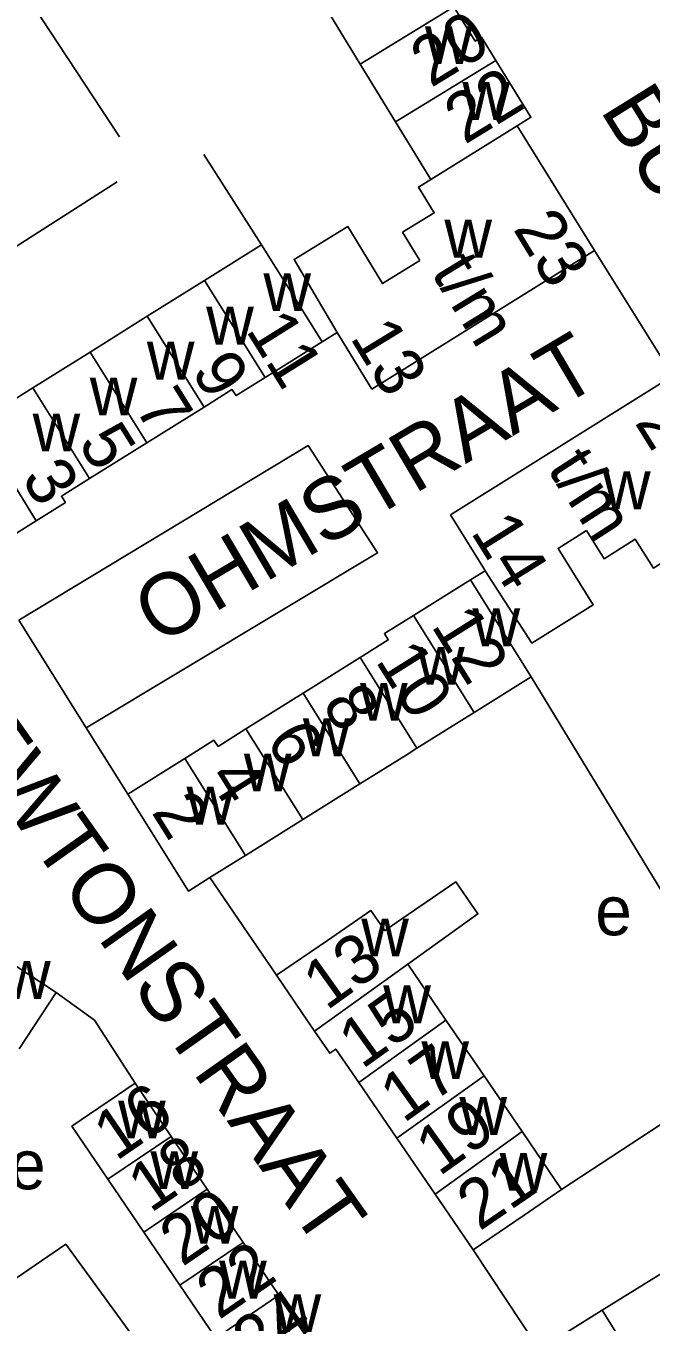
# Model space of a CAD drawing. Extents: x 159294 to 161936, y 384538 to 386517.
# Drawn here: x 159801.9 to 159852.7, y 385204 to 385309.2 of the extents above; entities that cross this region are included whole.
import ezdxf

# ---------------------------------------------------------------- set-up
doc = ezdxf.new("R2010")
doc.units = 0
for name, color, linetype in [('BLT_Basislijn', 7, 'Continuous'), ('BLT_Bebouwing', 7, 'Continuous'), ('BLT_Centroide', 7, 'Continuous'), ('BLT_Huisnummer', 7, 'Continuous'), ('BLT_Huisnummer_ tussenligend', 7, 'Continuous'), ('BLT_Huisnummer_reeks', 7, 'Continuous'), ('BLT_Onderverdeling_panden', 7, 'Continuous'), ('BLT_Straatnaam', 7, 'Continuous')]:
    doc.layers.add(name, color=color, linetype=linetype)

msp = doc.modelspace()

# ---------------------------------------------------------------- linework, layer by layer
at = {"layer": 'BLT_Basislijn'}
for p, q in [((159802.47, 385310.92), (159809.5, 385300.22)), ((159821.05, 385291.45), (159816.36, 385298.77)), ((159794.23, 385286.93), (159809.31, 385296.57)), ((159848.11, 385290.99), (159854.48, 385280.81)), ((159825.98, 385283.57), (159827.2, 385284.33)), ((159838.04, 385264.24), (159839.23, 385264.98)), ((159801.33, 385260.97), (159806.79, 385252.22)), ((159842.96, 385256.36), (159859.55, 385229.1)), ((159806.79, 385252.22), (159810.17, 385246.82)), ((159822.27, 385232.13), (159816.85, 385240.05)), ((159804.36, 385230.73), (159807.46, 385228.47)), ((159845.43, 385214.73), (159856.91, 385222.26)), ((159838.25, 385209.82), (159843.61, 385201.74))]:
    msp.add_line(p, q, dxfattribs=at)
for points in [[(159801.33, 385260.97), (159824.83, 385275.15), (159830.47, 385266.43), (159806.79, 385252.22)], [(159810.77, 385223.35), (159807.46, 385228.47)], [(159797.86, 385180.72), (159800.24, 385184.36), (159789.73, 385199.76), (159805.13, 385210.27), (159816, 385195.36), (159820.28, 385198.32)]]:
    msp.add_lwpolyline(points, dxfattribs=at)
at = {"layer": 'BLT_Bebouwing'}
for p, q in [((159829.06, 385306.13), (159826.2, 385310.83)), ((159831.93, 385301.44), (159829.06, 385306.13)), ((159834.8, 385296.75), (159831.93, 385301.44)), ((159841.81, 385301.11), (159844.96, 385296.05)), ((159844.96, 385296.05), (159848.11, 385290.99)), ((159816.41, 385288.55), (159821.05, 385291.45)), ((159848.11, 385290.99), (159830.02, 385279.71)), ((159811.76, 385285.65), (159816.41, 385288.55)), ((159807.11, 385282.74), (159811.76, 385285.65)), ((159821.34, 385280.67), (159825.98, 385283.57)), ((159802.46, 385279.83), (159807.11, 385282.74)), ((159854.48, 385280.81), (159836.39, 385269.52)), ((159797.82, 385276.93), (159802.46, 385279.83)), ((159811.72, 385275.36), (159816.37, 385278.27)), ((159807.07, 385272.46), (159811.72, 385275.36)), ((159798.09, 385266.14), (159802.74, 385269.04)), ((159838.04, 385264.24), (159833.4, 385261.34)), ((159829.07, 385257.94), (159824.42, 385255.04)), ((159838.32, 385253.46), (159842.96, 385256.36)), ((159824.42, 385255.04), (159819.78, 385252.13)), ((159833.68, 385250.56), (159838.32, 385253.46)), ((159814.82, 385249.74), (159810.17, 385246.82)), ((159824.39, 385244.76), (159829.03, 385247.66)), ((159819.74, 385241.86), (159824.39, 385244.76)), ((159832.93, 385233.02), (159836.03, 385228.48)), ((159825.36, 385227.59), (159822.27, 385232.13)), ((159836.03, 385228.48), (159839.13, 385223.95)), ((159810.77, 385223.35), (159813.69, 385219.04)), ((159832.05, 385218.88), (159828.94, 385223.41)), ((159839.13, 385223.95), (159842.23, 385219.42)), ((159813.69, 385219.04), (159816.62, 385214.74)), ((159835.15, 385214.35), (159832.05, 385218.88)), ((159842.23, 385219.42), (159845.43, 385214.73)), ((159808.56, 385215.56), (159811.49, 385211.25)), ((159816.62, 385214.74), (159819.54, 385210.43)), ((159838.25, 385209.82), (159835.15, 385214.35)), ((159811.49, 385211.25), (159814.41, 385206.95)), ((159819.54, 385210.43), (159822.46, 385206.13)), ((159848.73, 385204.93), (159853.84, 385208.1)), ((159814.41, 385206.95), (159817.34, 385202.64)), ((159822.46, 385206.13), (159825.39, 385201.82))]:
    msp.add_line(p, q, dxfattribs=at)
for points in [[(159836.67, 385310.78), (159838.41, 385307.99), (159838.91, 385308.3), (159840.08, 385306.42)], [(159840.08, 385306.42), (159842.94, 385301.81), (159841.81, 385301.11)], [(159833.92, 385290.16), (159832.51, 385292.47), (159835.08, 385294.04), (159833.81, 385296.13), (159834.8, 385296.75)], [(159827.2, 385284.33), (159823.69, 385290.26), (159828.06, 385292.92), (159830.88, 385288.3), (159833.92, 385290.16)], [(159821.05, 385291.45), (159823.33, 385287.81), (159825.98, 385283.57)], [(159830.02, 385279.71), (159827.41, 385283.98), (159827.2, 385284.33)], [(159816.37, 385278.27), (159818.64, 385279.69), (159818.97, 385279.2), (159821.34, 385280.67)], [(159802.74, 385269.04), (159805.1, 385270.51), (159804.78, 385271.03), (159807.07, 385272.46)], [(159836.39, 385269.52), (159839.04, 385265.28), (159839.23, 385264.98)], [(159839.23, 385264.98), (159843.02, 385259.1), (159848, 385262.21), (159845.14, 385266.79), (159847.45, 385268.24)], [(159847.45, 385268.24), (159848.88, 385265.95), (159851.42, 385267.54), (159852.89, 385265.19), (159854.29, 385266.07)], [(159842.96, 385256.36), (159840.69, 385260), (159838.04, 385264.24)], [(159833.4, 385261.34), (159831.03, 385259.87), (159831.34, 385259.36), (159829.07, 385257.94)], [(159819.78, 385252.13), (159817.51, 385250.71), (159817.18, 385251.21), (159815.24, 385250), (159814.82, 385249.74)], [(159829.03, 385247.66), (159832.79, 385250), (159833.68, 385250.56)], [(159810.17, 385246.82), (159815.1, 385238.96), (159816.85, 385240.05)], [(159816.85, 385240.05), (159819.34, 385241.6), (159819.74, 385241.86)], [(159822.27, 385232.13), (159826.4, 385234.95), (159829.94, 385237.38), (159831.06, 385235.75), (159836.84, 385239.71), (159838.63, 385237.1), (159832.93, 385233.02)], [(159796.65, 385235.77), (159804.36, 385230.73)], [(159804.36, 385230.73), (159801.36, 385226.16)], [(159828.94, 385223.41), (159827.08, 385226.13), (159826.59, 385225.79), (159825.36, 385227.59)], [(159810.77, 385223.35), (159805.64, 385219.86), (159808.56, 385215.56)], [(159845.43, 385214.73), (159842.38, 385212.64), (159838.25, 385209.82)], [(159848.73, 385204.93), (159847.86, 385204.38), (159843.61, 385201.74)]]:
    msp.add_lwpolyline(points, dxfattribs=at)
at = {"layer": 'BLT_Onderverdeling_panden'}
for p, q in [((159829.06, 385306.13), (159836.67, 385310.78)), ((159831.93, 385301.44), (159840.08, 385306.42)), ((159841.81, 385301.11), (159834.8, 385296.75)), ((159821.34, 385280.67), (159816.41, 385288.55)), ((159816.37, 385278.27), (159811.76, 385285.65)), ((159811.72, 385275.36), (159807.11, 385282.74)), ((159807.07, 385272.46), (159802.46, 385279.83)), ((159802.74, 385269.04), (159797.82, 385276.93)), ((159838.32, 385253.46), (159833.4, 385261.34)), ((159833.68, 385250.56), (159829.07, 385257.94)), ((159829.03, 385247.66), (159824.42, 385255.04)), ((159824.39, 385244.76), (159819.78, 385252.13)), ((159819.74, 385241.86), (159814.82, 385249.74)), ((159825.36, 385227.59), (159832.93, 385233.02)), ((159828.94, 385223.41), (159836.03, 385228.48)), ((159832.05, 385218.88), (159839.13, 385223.95)), ((159808.56, 385215.56), (159813.69, 385219.04)), ((159835.15, 385214.35), (159842.23, 385219.42)), ((159811.49, 385211.25), (159816.62, 385214.74)), ((159814.41, 385206.95), (159819.54, 385210.43)), ((159817.34, 385202.64), (159822.46, 385206.13)), ((159853.96, 385196.48), (159848.73, 385204.93))]:
    msp.add_line(p, q, dxfattribs=at)

# ---------------------------------------------------------------- texts
at = {"layer": 'BLT_Centroide'}
for s, p in [('w', (159834.33, 385306.12)), ('w', (159837.37, 385301.59)), ('w', (159835.91, 385290.41)), ('w', (159821.2, 385286.06)), ('w', (159816.55, 385283.34)), ('w', (159811.73, 385280.5)), ('w', (159807.09, 385277.59)), ('w', (159802.44, 385274.67)), ('w', (159848.8, 385269.97)), ('w', (159838.19, 385258.84)), ('w', (159833.69, 385255.72)), ('w', (159829.05, 385252.8)), ('w', (159824.41, 385249.91)), ('w', (159819.61, 385247.05)), ('w', (159814.95, 385244.36)), ('e', (159848.17, 385235.37)), ('w', (159829.15, 385233.66)), ('w', (159800.04, 385230.2)), ('w', (159830.94, 385228.22)), ('w', (159834.04, 385223.69)), ('w', (159837.13, 385219.16)), ('w', (159809.39, 385218.87)), ('e', (159800.53, 385214.74)), ('w', (159812.02, 385214.76)), ('w', (159840.4, 385214.62)), ('w', (159815.3, 385210.32)), ('w', (159817.6, 385205.86)), ('w', (159822.03, 385203.15))]:
    msp.add_text(s, height=4, dxfattribs=at).set_placement(p)
at = {"layer": 'BLT_Huisnummer'}
for s, rotation, p in [('22', 31.4114, (159837.55, 385299.55)), ('11', 301.9942, (159819.71, 385284.52)), ('5', 302.0224, (159806.07, 385275.34)), ('12', 301.9819, (159834.78, 385260.52)), ('6', 301.9795, (159821.33, 385251.2)), ('2', 302.0721, (159812.05, 385245.39)), ('13', 35.6158, (159826.32, 385229.2)), ('17', 35.6134, (159832.58, 385220.05)), ('16', 34.3877, (159809.22, 385216.98)), ('21', 34.3669, (159838.76, 385211.3)), ('20', 34.3877, (159814.6, 385208.4)), ('24', 34.3877, (159820.51, 385200.2))]:
    msp.add_text(s, height=4, rotation=rotation, dxfattribs=at).set_placement(p)
at = {"layer": 'BLT_Huisnummer_ tussenligend'}
for s, rotation, p in [('20', 31.4114, (159834.81, 385304.16)), ('9', 302.0021, (159815.28, 385281.18)), ('7', 302.0021, (159810.67, 385278.23)), ('3', 302.0224, (159801.46, 385272.48)), ('10', 301.9795, (159830.25, 385257.67)), ('8', 301.9795, (159825.89, 385254.14)), ('4', 302.0721, (159816.6, 385248.2)), ('15', 35.6158, (159829.21, 385224.44)), ('19', 35.6134, (159835.48, 385215.73)), ('18', 34.3877, (159812.01, 385212.75)), ('22', 34.3877, (159817.57, 385204.09))]:
    msp.add_text(s, height=4, rotation=rotation, dxfattribs=at).set_placement(p)
at = {"layer": 'BLT_Huisnummer_reeks'}
for s, rotation, p in [('23', 301.4138, (159841.44, 385292.75)), ('t/m', 301.4138, (159834.78, 385289.21)), ('13', 301.4138, (159828.19, 385283.92)), ('24', 302.0212, (159851.32, 385277.02)), ('t/m', 302.7713, (159844.2, 385273.28)), ('14', 302.0212, (159837.99, 385268.13))]:
    msp.add_text(s, height=4, rotation=rotation, dxfattribs=at).set_placement(p)
at = {"layer": 'BLT_Straatnaam'}
for s, rotation, p in [('BUIJS BALLOTSTRAAT', 301.9045, (159848.5, 385302.4)), ('OHMSTRAAT', 30.6121, (159812.68, 385258.87)), ('NEWTONSTRAAT', 305.2811, (159793.3, 385255.48))]:
    msp.add_text(s, height=5, rotation=rotation, dxfattribs=at).set_placement(p)

doc.saveas('drawing.dxf')
